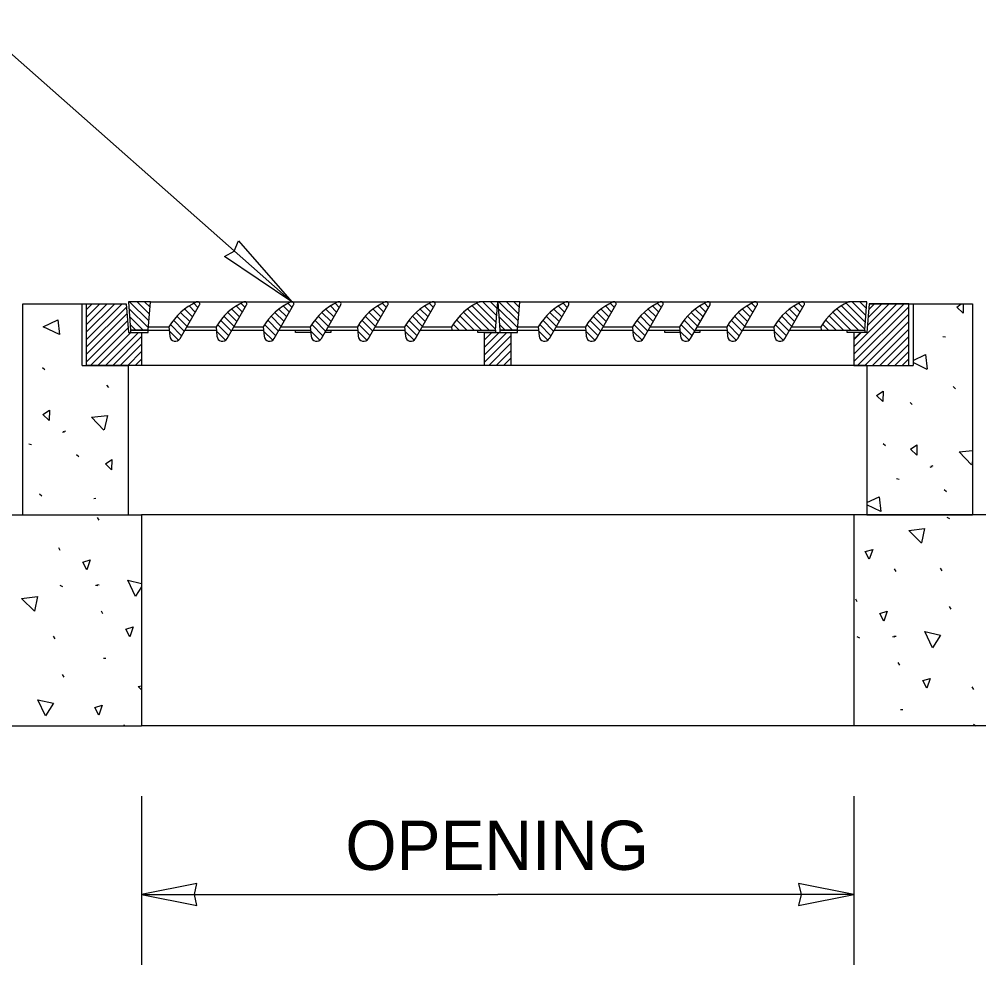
# Model space of a CAD drawing. Extents: x 99862 to 103151, y 100000 to 102076.
# Drawn here: x 101249.5 to 101522.3, y 100505.3 to 100774.3 of the extents above; entities that cross this region are included whole.
import ezdxf

# ---------------------------------------------------------------- set-up
doc = ezdxf.new("R2010")
doc.units = 0
for name, color, linetype in [('Level 1', 7, 'Continuous'), ('Level 11', 7, 'Continuous'), ('Level 15', 7, 'Continuous'), ('Level 17', 7, 'Continuous'), ('Level 2', 7, 'Continuous'), ('Level 20', 7, 'Continuous'), ('Level 5', 7, 'Continuous'), ('Level 7', 7, 'Continuous')]:
    doc.layers.add(name, color=color, linetype=linetype)

msp = doc.modelspace()

# ---------------------------------------------------------------- linework, layer by layer
at = {"layer": 'Level 1'}
for p, q in [((101286.78, 100693.97), (101380.53, 100693.97)), ((101391.78, 100693.97), (101485.53, 100693.97)), ((101286.16, 100685.84), (101292.16, 100685.84)), ((101286.23, 100686.81), (101292.07, 100686.81)), ((101296.57, 100685.84), (101305.55, 100685.84)), ((101297.13, 100686.81), (101305.47, 100686.81)), ((101309.96, 100685.84), (101318.94, 100685.84)), ((101310.52, 100686.81), (101318.86, 100686.81)), ((101323.36, 100685.84), (101332.34, 100685.84)), ((101323.91, 100686.81), (101332.25, 100686.81)), ((101336.75, 100685.84), (101345.73, 100685.84)), ((101337.3, 100686.81), (101345.65, 100686.81)), ((101350.14, 100685.84), (101359.12, 100685.84)), ((101350.7, 100686.81), (101359.04, 100686.81)), ((101363.53, 100685.84), (101372.51, 100685.84)), ((101364.09, 100686.81), (101372.43, 100686.81)), ((101391.16, 100685.84), (101397.16, 100685.84)), ((101391.23, 100686.81), (101397.07, 100686.81)), ((101401.57, 100685.84), (101410.55, 100685.84)), ((101402.13, 100686.81), (101410.47, 100686.81)), ((101414.96, 100685.84), (101423.94, 100685.84)), ((101415.52, 100686.81), (101423.86, 100686.81)), ((101428.36, 100685.84), (101437.34, 100685.84)), ((101428.91, 100686.81), (101437.25, 100686.81)), ((101441.75, 100685.84), (101450.73, 100685.84)), ((101442.3, 100686.81), (101450.65, 100686.81)), ((101455.14, 100685.84), (101464.12, 100685.84)), ((101455.7, 100686.81), (101464.04, 100686.81)), ((101468.53, 100685.84), (101477.51, 100685.84)), ((101469.09, 100686.81), (101477.43, 100686.81))]:
    msp.add_line(p, q, dxfattribs=at)
at = {"layer": 'Level 11'}
for points in [[(101281.16, 100685.22), (101286.16, 100685.22), (101286.16, 100685.84), (101281.16, 100685.84)], [(101384.91, 100685.22), (101379.91, 100685.22), (101379.91, 100685.84), (101384.91, 100685.84)], [(101386.16, 100685.22), (101391.16, 100685.22), (101391.16, 100685.84), (101386.16, 100685.84)], [(101489.91, 100685.22), (101484.91, 100685.22), (101484.91, 100685.84), (101489.91, 100685.84)]]:
    msp.add_lwpolyline(points, close=True, dxfattribs=at)
for points in [[(101332.39, 100685.22), (101328.03, 100685.22), (101328.03, 100685.84), (101332.34, 100685.84)], [(101336.75, 100685.84), (101338.04, 100685.84), (101338.04, 100685.22), (101336.39, 100685.22)], [(101437.39, 100685.22), (101433.03, 100685.22), (101433.03, 100685.84), (101437.34, 100685.84)], [(101441.75, 100685.84), (101443.04, 100685.84), (101443.04, 100685.22), (101441.39, 100685.22)]]:
    msp.add_lwpolyline(points, dxfattribs=at)
at = {"layer": 'Level 15'}
for p, q in [((101284.28, 100553.34), (101284.28, 100505.34)), ((101486.78, 100553.34), (101486.78, 100505.34)), ((101284.28, 100525.34), (101385.53, 100525.34)), ((101486.78, 100525.34), (101385.53, 100525.34))]:
    msp.add_line(p, q, dxfattribs=at)
msp.add_lwpolyline([(101326.96, 100693.97), (101236.03, 100774.32), (101220.03, 100774.32)], dxfattribs=at)
for points in [[(101326.96, 100693.97), (101307.87, 100706.82), (101310.63, 100708.37), (101311.81, 100711.3)], [(101284.28, 100525.34), (101300.01, 100522.26), (101299.28, 100525.34), (101300.01, 100528.43)], [(101486.78, 100525.34), (101471.06, 100528.43), (101471.79, 100525.34), (101471.06, 100522.26)]]:
    msp.add_lwpolyline(points, close=True, dxfattribs=at)
at = {"layer": 'Level 17'}
for p, q in [((101286.36, 100688.49), (101280.88, 100693.97)), ((101286.51, 100690.46), (101283, 100693.97)), ((101286.67, 100692.43), (101285.13, 100693.97)), ((101385.23, 100690.06), (101381.33, 100693.97)), ((101385.39, 100692.03), (101383.45, 100693.97)), ((101391.36, 100688.49), (101385.88, 100693.97)), ((101391.51, 100690.46), (101388, 100693.97)), ((101391.67, 100692.43), (101390.13, 100693.97)), ((101490.23, 100690.06), (101486.33, 100693.97)), ((101490.39, 100692.03), (101488.45, 100693.97)), ((101268.66, 100691.73), (101270.27, 100693.34)), ((101268.66, 100689.61), (101272.4, 100693.34)), ((101268.66, 100687.48), (101274.52, 100693.34)), ((101268.66, 100685.36), (101276.64, 100693.34)), ((101268.66, 100683.24), (101278.76, 100693.34)), ((101268.66, 100681.12), (101279.98, 100692.44)), ((101286.21, 100686.52), (101280.68, 100692.05)), ((101298.76, 100689.64), (101296.53, 100691.87)), ((101299.54, 100690.98), (101297.77, 100692.74)), ((101300.31, 100692.33), (101299.12, 100693.52)), ((101312.15, 100689.64), (101309.92, 100691.87)), ((101312.93, 100690.98), (101311.17, 100692.74)), ((101313.71, 100692.33), (101312.51, 100693.52)), ((101325.55, 100689.64), (101323.31, 100691.87)), ((101326.32, 100690.98), (101324.56, 100692.74)), ((101327.1, 100692.33), (101325.9, 100693.52)), ((101338.94, 100689.64), (101336.71, 100691.87)), ((101339.72, 100690.98), (101337.95, 100692.74)), ((101340.49, 100692.33), (101339.3, 100693.52)), ((101352.33, 100689.64), (101350.1, 100691.87)), ((101353.11, 100690.98), (101351.35, 100692.74)), ((101353.88, 100692.33), (101352.69, 100693.52)), ((101365.72, 100689.64), (101363.49, 100691.87)), ((101366.5, 100690.98), (101364.74, 100692.74)), ((101367.28, 100692.33), (101366.08, 100693.52)), ((101380.97, 100685.84), (101375.82, 100690.99)), ((101383.09, 100685.84), (101376.99, 100691.95)), ((101384.93, 100686.12), (101378.24, 100692.81)), ((101385.08, 100688.09), (101379.59, 100693.58)), ((101391.21, 100686.52), (101385.68, 100692.05)), ((101403.76, 100689.64), (101401.53, 100691.87)), ((101404.54, 100690.98), (101402.77, 100692.74)), ((101405.31, 100692.33), (101404.12, 100693.52)), ((101417.15, 100689.64), (101414.92, 100691.87)), ((101417.93, 100690.98), (101416.17, 100692.74)), ((101418.71, 100692.33), (101417.51, 100693.52)), ((101430.55, 100689.64), (101428.31, 100691.87)), ((101431.32, 100690.98), (101429.56, 100692.74)), ((101432.1, 100692.33), (101430.9, 100693.52)), ((101443.94, 100689.64), (101441.71, 100691.87)), ((101444.72, 100690.98), (101442.95, 100692.74)), ((101445.49, 100692.33), (101444.3, 100693.52)), ((101457.33, 100689.64), (101455.1, 100691.87)), ((101458.11, 100690.98), (101456.35, 100692.74)), ((101458.88, 100692.33), (101457.69, 100693.52)), ((101470.72, 100689.64), (101468.49, 100691.87)), ((101471.5, 100690.98), (101469.74, 100692.74)), ((101472.28, 100692.33), (101471.08, 100693.52)), ((101485.97, 100685.84), (101480.82, 100690.99)), ((101488.09, 100685.84), (101481.99, 100691.95)), ((101489.93, 100686.12), (101483.24, 100692.81)), ((101490.08, 100688.09), (101484.59, 100693.58)), ((101486.78, 100681.15), (101498.98, 100693.34)), ((101486.78, 100679.03), (101501.1, 100693.34)), ((101486.78, 100676.91), (101502.41, 100692.53)), ((101490.68, 100687.17), (101496.86, 100693.34)), ((101490.86, 100689.47), (101494.74, 100693.34)), ((101491.04, 100691.77), (101492.62, 100693.34)), ((101268.66, 100679), (101280.13, 100690.47)), ((101268.66, 100676.88), (101280.28, 100688.5)), ((101284.77, 100685.84), (101280.86, 100689.75)), ((101296.43, 100685.6), (101293.34, 100688.69)), ((101297.21, 100686.95), (101294.31, 100689.84)), ((101297.98, 100688.29), (101295.38, 100690.9)), ((101309.82, 100685.6), (101306.74, 100688.69)), ((101310.6, 100686.95), (101307.71, 100689.84)), ((101311.38, 100688.29), (101308.77, 100690.9)), ((101323.22, 100685.6), (101320.13, 100688.69)), ((101323.99, 100686.95), (101321.1, 100689.84)), ((101324.77, 100688.29), (101322.16, 100690.9)), ((101336.61, 100685.6), (101333.52, 100688.69)), ((101337.39, 100686.95), (101334.49, 100689.84)), ((101338.16, 100688.29), (101335.55, 100690.9)), ((101350, 100685.6), (101346.91, 100688.69)), ((101350.78, 100686.95), (101347.88, 100689.84)), ((101351.56, 100688.29), (101348.95, 100690.9)), ((101363.4, 100685.6), (101360.31, 100688.69)), ((101364.17, 100686.95), (101361.28, 100689.84)), ((101364.95, 100688.29), (101362.34, 100690.9)), ((101376.73, 100685.84), (101373.78, 100688.79)), ((101378.85, 100685.84), (101374.76, 100689.93)), ((101389.77, 100685.84), (101385.86, 100689.75)), ((101401.43, 100685.6), (101398.34, 100688.69)), ((101402.21, 100686.95), (101399.31, 100689.84)), ((101402.98, 100688.29), (101400.38, 100690.9)), ((101414.82, 100685.6), (101411.74, 100688.69)), ((101415.6, 100686.95), (101412.71, 100689.84)), ((101416.38, 100688.29), (101413.77, 100690.9)), ((101428.22, 100685.6), (101425.13, 100688.69)), ((101428.99, 100686.95), (101426.1, 100689.84)), ((101429.77, 100688.29), (101427.16, 100690.9)), ((101441.61, 100685.6), (101438.52, 100688.69)), ((101442.39, 100686.95), (101439.49, 100689.84)), ((101443.16, 100688.29), (101440.55, 100690.9)), ((101455, 100685.6), (101451.91, 100688.69)), ((101455.78, 100686.95), (101452.88, 100689.84)), ((101456.56, 100688.29), (101453.95, 100690.9)), ((101468.4, 100685.6), (101465.31, 100688.69)), ((101469.17, 100686.95), (101466.28, 100689.84)), ((101469.95, 100688.29), (101467.34, 100690.9)), ((101481.73, 100685.84), (101478.78, 100688.79)), ((101483.85, 100685.84), (101479.76, 100689.93)), ((101487.84, 100675.84), (101502.41, 100690.41)), ((101489.96, 100675.84), (101502.41, 100688.29)), ((101269.75, 100675.84), (101280.43, 100686.53)), ((101282.64, 100685.84), (101281.04, 100687.45)), ((101294.78, 100683.01), (101292.18, 100685.61)), ((101295.65, 100684.26), (101292.47, 100687.45)), ((101308.17, 100683.01), (101305.57, 100685.61)), ((101309.05, 100684.26), (101305.86, 100687.45)), ((101321.56, 100683.01), (101318.96, 100685.61)), ((101322.44, 100684.26), (101319.25, 100687.45)), ((101334.96, 100683.01), (101332.36, 100685.61)), ((101335.83, 100684.26), (101332.64, 100687.45)), ((101348.35, 100683.01), (101345.75, 100685.61)), ((101349.23, 100684.26), (101346.04, 100687.45)), ((101361.74, 100683.01), (101359.14, 100685.61)), ((101362.62, 100684.26), (101359.43, 100687.45)), ((101374.6, 100685.84), (101372.89, 100687.55)), ((101387.64, 100685.84), (101386.04, 100687.45)), ((101399.78, 100683.01), (101397.18, 100685.61)), ((101400.65, 100684.26), (101397.47, 100687.45)), ((101413.17, 100683.01), (101410.57, 100685.61)), ((101414.05, 100684.26), (101410.86, 100687.45)), ((101426.56, 100683.01), (101423.96, 100685.61)), ((101427.44, 100684.26), (101424.25, 100687.45)), ((101439.96, 100683.01), (101437.36, 100685.61)), ((101440.83, 100684.26), (101437.64, 100687.45)), ((101453.35, 100683.01), (101450.75, 100685.61)), ((101454.23, 100684.26), (101451.04, 100687.45)), ((101466.74, 100683.01), (101464.14, 100685.61)), ((101467.62, 100684.26), (101464.43, 100687.45)), ((101479.6, 100685.84), (101477.89, 100687.55)), ((101492.09, 100675.84), (101502.41, 100686.17)), ((101271.87, 100675.84), (101281.24, 100685.22)), ((101273.99, 100675.84), (101283.36, 100685.22)), ((101276.11, 100675.84), (101284.28, 100684.02)), ((101381.78, 100683.14), (101383.87, 100685.22)), ((101381.78, 100681.02), (101385.99, 100685.22)), ((101381.78, 100678.89), (101388.11, 100685.22)), ((101381.78, 100676.77), (101389.28, 100684.27)), ((101486.78, 100683.27), (101488.73, 100685.22)), ((101486.78, 100683.14), (101488.87, 100685.22)), ((101494.21, 100675.84), (101502.41, 100684.05)), ((101278.23, 100675.84), (101284.28, 100681.9)), ((101382.98, 100675.84), (101389.28, 100682.15)), ((101385.1, 100675.84), (101389.28, 100680.03)), ((101496.33, 100675.84), (101502.41, 100681.92)), ((101280.35, 100675.84), (101284.28, 100679.78)), ((101282.47, 100675.84), (101284.28, 100677.65)), ((101387.22, 100675.84), (101389.28, 100677.91)), ((101498.45, 100675.84), (101502.41, 100679.8)), ((101500.57, 100675.84), (101502.41, 100677.68))]:
    msp.add_line(p, q, dxfattribs=at)
at = {"layer": 'Level 2'}
for points in [[(101286.16, 100685.84), (101286.78, 100693.97), (101280.53, 100693.97), (101281.16, 100685.84), (101286.16, 100685.84)], [(101372.43, 100686.81), (101372.51, 100685.84), (101384.91, 100685.84), (101385.53, 100693.97), (101380.53, 100693.97)], [(101391.16, 100685.84), (101391.78, 100693.97), (101385.53, 100693.97), (101386.16, 100685.84), (101391.16, 100685.84)], [(101477.43, 100686.81), (101477.51, 100685.84), (101489.91, 100685.84), (101490.53, 100693.97), (101485.53, 100693.97)], [(101268.66, 100675.84), (101268.66, 100693.34)], [(101268.66, 100693.34), (101279.91, 100693.34)], [(101279.91, 100693.34), (101280.53, 100685.22)], [(101295.22, 100683.5), (101300.72, 100693.03)], [(101308.61, 100683.5), (101314.11, 100693.03)], [(101322, 100683.5), (101327.5, 100693.03)], [(101335.39, 100683.5), (101340.9, 100693.03)], [(101348.79, 100683.5), (101354.29, 100693.03)], [(101362.18, 100683.5), (101367.68, 100693.03)], [(101400.22, 100683.5), (101405.72, 100693.03)], [(101413.61, 100683.5), (101419.11, 100693.03)], [(101427, 100683.5), (101432.5, 100693.03)], [(101440.39, 100683.5), (101445.9, 100693.03)], [(101453.79, 100683.5), (101459.29, 100693.03)], [(101467.18, 100683.5), (101472.68, 100693.03)], [(101491.16, 100693.34), (101490.53, 100685.22)], [(101502.41, 100693.34), (101491.16, 100693.34)], [(101502.41, 100675.84), (101502.41, 100693.34)], [(101292.07, 100686.81), (101292.31, 100684.14)], [(101305.47, 100686.81), (101305.7, 100684.14)], [(101318.86, 100686.81), (101319.09, 100684.14)], [(101332.25, 100686.81), (101332.49, 100684.14)], [(101345.65, 100686.81), (101345.88, 100684.14)], [(101359.04, 100686.81), (101359.27, 100684.14)], [(101397.07, 100686.81), (101397.31, 100684.14)], [(101410.47, 100686.81), (101410.7, 100684.14)], [(101423.86, 100686.81), (101424.09, 100684.14)], [(101437.25, 100686.81), (101437.49, 100684.14)], [(101450.65, 100686.81), (101450.88, 100684.14)], [(101464.04, 100686.81), (101464.27, 100684.14)], [(101280.53, 100685.22), (101284.28, 100685.22)], [(101284.28, 100685.22), (101284.28, 100675.84)], [(101381.78, 100675.84), (101381.78, 100685.22)], [(101381.78, 100685.22), (101389.28, 100685.22)], [(101389.28, 100685.22), (101389.28, 100675.84)], [(101486.78, 100685.22), (101486.78, 100675.84)], [(101490.53, 100685.22), (101486.78, 100685.22)], [(101284.28, 100675.84), (101268.66, 100675.84)], [(101389.28, 100675.84), (101381.78, 100675.84)], [(101486.78, 100675.84), (101502.41, 100675.84)]]:
    msp.add_lwpolyline(points, dxfattribs=at)
for centre, radius, start, end in [((101307.19, 100677.99), 17.5, 114.5682, 149.7715), ((101300.18, 100693.34), 0.625, 330, 114.5682), ((101320.59, 100677.99), 17.5, 114.5682, 149.7715), ((101313.57, 100693.34), 0.625, 330, 114.5682), ((101333.98, 100677.99), 17.5, 114.5682, 149.7715), ((101326.96, 100693.34), 0.625, 330, 114.5682), ((101347.37, 100677.99), 17.5, 114.5682, 149.7715), ((101340.36, 100693.34), 0.625, 330, 114.5682), ((101360.77, 100677.99), 17.5, 114.5682, 149.7715), ((101353.75, 100693.34), 0.625, 330, 114.5682), ((101374.16, 100677.99), 17.5, 114.5682, 149.7715), ((101367.14, 100693.34), 0.625, 330, 114.5682), ((101387.55, 100677.99), 17.5, 114.5682, 149.7715), ((101380.53, 100693.34), 0.625, 90, 114.5682), ((101412.19, 100677.99), 17.5, 114.5682, 149.7715), ((101405.18, 100693.34), 0.625, 330, 114.5682), ((101425.59, 100677.99), 17.5, 114.5682, 149.7715), ((101418.57, 100693.34), 0.625, 330, 114.5682), ((101438.98, 100677.99), 17.5, 114.5682, 149.7715), ((101431.96, 100693.34), 0.625, 330, 114.5682), ((101452.37, 100677.99), 17.5, 114.5682, 149.7715), ((101445.36, 100693.34), 0.625, 330, 114.5682), ((101465.77, 100677.99), 17.5, 114.5682, 149.7715), ((101458.75, 100693.34), 0.625, 330, 114.5682), ((101479.16, 100677.99), 17.5, 114.5682, 149.7715), ((101472.14, 100693.34), 0.625, 330, 114.5682), ((101492.55, 100677.99), 17.5, 114.5682, 149.7715), ((101485.53, 100693.34), 0.625, 90, 114.5682), ((101293.86, 100684.28), 1.56, 185, 330), ((101307.26, 100684.28), 1.56, 185, 330), ((101320.65, 100684.28), 1.56, 185, 330), ((101334.04, 100684.28), 1.56, 185, 330), ((101347.43, 100684.28), 1.56, 185, 330), ((101360.83, 100684.28), 1.56, 185, 330), ((101398.86, 100684.28), 1.56, 185, 330), ((101412.26, 100684.28), 1.56, 185, 330), ((101425.65, 100684.28), 1.56, 185, 330), ((101439.04, 100684.28), 1.56, 185, 330), ((101452.43, 100684.28), 1.56, 185, 330), ((101465.83, 100684.28), 1.56, 185, 330)]:
    msp.add_arc(centre, radius, start, end, dxfattribs=at)
at = {"layer": 'Level 5'}
for p, q in [((101105.1, 100633.34), (101284.28, 100633.34)), ((101272.18, 100631.79), (101271.75, 100632.55)), ((101284.28, 100633.34), (101284.28, 100573.34)), ((101665.1, 100633.34), (101486.78, 100633.34)), ((101486.78, 100633.34), (101486.78, 100573.34)), ((101513.27, 100632.7), (101513.96, 100632.29)), ((101261.15, 100623.2), (101260.72, 100623.96)), ((101498.78, 100617.18), (101498.36, 100617.94)), ((101511.87, 100617.43), (101511.45, 100618.2)), ((101261.06, 100613.33), (101261.76, 100612.92)), ((101271.16, 100613.32), (101271.8, 100613.28)), ((101271.53, 100613.48), (101272.17, 100613.44)), ((101487.75, 100608.59), (101487.33, 100609.35)), ((101514.43, 100606.5), (101514.01, 100607.26)), ((101273.26, 100605.17), (101272.84, 100605.94)), ((101259.67, 100598.07), (101259.24, 100598.83)), ((101487.67, 100598.73), (101488.36, 100598.32)), ((101497.76, 100598.71), (101498.4, 100598.67)), ((101498.14, 100598.87), (101498.78, 100598.83)), ((101273.45, 100592.58), (101274.08, 100592.54)), ((101499.86, 100590.56), (101499.44, 100591.33)), ((101262.23, 100587.13), (101261.8, 100587.9)), ((101520.88, 100583.63), (101520.45, 100584.39)), ((101500.05, 100577.97), (101500.69, 100577.93)), ((101279.43, 100573.34), (101279.28, 100573.62)), ((101520.8, 100573.76), (101521.49, 100573.35)), ((101125.1, 100573.34), (101284.28, 100573.34)), ((101645.1, 100573.34), (101486.78, 100573.34))]:
    msp.add_line(p, q, dxfattribs=at)
for points in [[(101506.02, 100625.25), (101502.39, 100628.87), (101506.92, 100629.43), (101506.04, 100625.34)], [(101491.16, 100620.72), (101490.03, 100622.91), (101492.16, 100623.52), (101491.16, 100620.72)], [(101268.7, 100617.73), (101267.57, 100619.92), (101269.7, 100620.53), (101268.7, 100617.73)], [(101282.53, 100610.09), (101280.35, 100614.73), (101284.28, 100613.83)], [(101284.28, 100612.88), (101282.58, 100610.16)], [(101253.81, 100605.89), (101250.18, 100609.51), (101254.72, 100610.07), (101253.84, 100605.97)], [(101495.3, 100603.12), (101494.17, 100605.31), (101496.3, 100605.92), (101495.3, 100603.12)], [(101280.9, 100598.64), (101279.77, 100600.82), (101281.9, 100601.44), (101280.9, 100598.64)], [(101509.13, 100595.48), (101506.96, 100600.12), (101511.41, 100599.1), (101509.18, 100595.55)], [(101284.28, 100583.57), (101283.31, 100584.54), (101284.28, 100584.66)], [(101507.5, 100584.03), (101506.37, 100586.21), (101508.51, 100586.83), (101507.5, 100584.03)], [(101256.93, 100576.12), (101254.75, 100580.76), (101259.21, 100579.74), (101256.98, 100576.19)], [(101272.09, 100576.39), (101270.95, 100578.58), (101273.09, 100579.19), (101272.09, 100576.39)]]:
    msp.add_lwpolyline(points, dxfattribs=at)
at = {"layer": 'Level 7'}
for p, q in [((101250.53, 100633.34), (101250.53, 100693.34)), ((101250.53, 100693.34), (101267.41, 100693.34)), ((101267.41, 100675.84), (101267.41, 100693.34)), ((101267.41, 100693.34), (101279.91, 100693.34)), ((101491.16, 100693.34), (101503.66, 100693.34)), ((101503.66, 100693.34), (101503.66, 100675.84)), ((101503.66, 100693.34), (101520.53, 100693.34)), ((101520.53, 100693.34), (101520.53, 100633.34)), ((101512.07, 100684.1), (101512.85, 100683.94)), ((101256.73, 100674.6), (101256.08, 100675.19)), ((101267.41, 100675.84), (101280.53, 100675.84)), ((101280.53, 100633.34), (101280.53, 100675.84)), ((101490.53, 100675.84), (101280.53, 100675.84)), ((101490.53, 100675.84), (101490.53, 100633.34)), ((101490.53, 100675.84), (101503.66, 100675.84)), ((101275.01, 100669.6), (101274.36, 100670.18)), ((101515.71, 100669.21), (101515.06, 100669.8)), ((101503.42, 100664.71), (101502.77, 100665.3)), ((101261.78, 100656.81), (101262.4, 100656.98)), ((101262.08, 100657.08), (101262.7, 100657.25)), ((101252.23, 100653.54), (101253.02, 100653.37)), ((101495.79, 100653), (101495.14, 100653.58)), ((101266.42, 100649.79), (101265.77, 100650.37)), ((101508.77, 100647.19), (101509.39, 100647.36)), ((101508.47, 100646.92), (101509.09, 100647.09)), ((101498.92, 100643.64), (101499.71, 100643.48)), ((101255.88, 100638.65), (101255.23, 100639.23)), ((101513.11, 100639.9), (101512.46, 100640.48)), ((101270.7, 100637.94), (101271.31, 100638.12)), ((101250.53, 100633.34), (101280.53, 100633.34)), ((101486.78, 100633.34), (101284.28, 100633.34)), ((101490.53, 100633.34), (101520.53, 100633.34)), ((101486.78, 100573.34), (101284.28, 100573.34))]:
    msp.add_line(p, q, dxfattribs=at)
for points in [[(101517.85, 100690.74), (101516.07, 100692.44), (101517.35, 100693.34)], [(101517.88, 100693.34), (101517.85, 100690.74)], [(101260.95, 100684.59), (101256.34, 100686.83), (101260.44, 100688.84), (101260.94, 100684.68)], [(101503.66, 100677.25), (101507.13, 100678.95), (101507.63, 100674.79)], [(101507.63, 100674.7), (101503.66, 100676.63)], [(101495.06, 100665.58), (101493.28, 100667.28), (101495.1, 100668.55), (101495.06, 100665.58)], [(101258.02, 100660.18), (101256.24, 100661.88), (101258.06, 100663.15), (101258.02, 100660.18)], [(101273.58, 100657.46), (101270.02, 100661.13), (101274.56, 100661.62), (101273.61, 100657.54)], [(101504.71, 100650.29), (101502.93, 100651.99), (101504.74, 100653.26), (101504.71, 100650.29)], [(101520.27, 100647.56), (101516.7, 100651.24), (101520.53, 100651.65)], [(101275.77, 100646.1), (101273.99, 100647.8), (101275.81, 100649.07), (101275.77, 100646.1)], [(101520.53, 100648.67), (101520.3, 100647.65)], [(101490.53, 100636.8), (101493.98, 100638.49), (101494.48, 100634.33)], [(101494.49, 100634.25), (101490.53, 100636.16)]]:
    msp.add_lwpolyline(points, dxfattribs=at)

# ---------------------------------------------------------------- texts
at = {"layer": 'Level 20'}
msp.add_text('OPENING', height=14, rotation=360, dxfattribs=at).set_placement((101342.22, 100532.34))

doc.saveas('drawing.dxf')
